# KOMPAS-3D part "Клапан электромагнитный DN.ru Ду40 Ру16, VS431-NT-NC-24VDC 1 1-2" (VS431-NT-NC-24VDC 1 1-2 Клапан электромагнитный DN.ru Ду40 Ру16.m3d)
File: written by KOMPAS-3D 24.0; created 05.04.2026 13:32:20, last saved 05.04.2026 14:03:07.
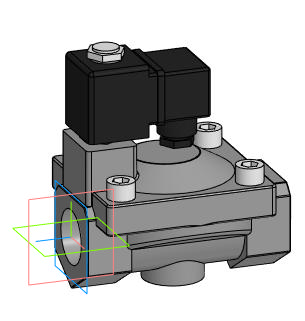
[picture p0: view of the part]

Document properties: Автор: artio; Полное имя файла: C:\Users\artio\OneDrive\Рабочий стол\Клапан электромагнитный DN.ru\VS431\VS431-NT-NC\VS431-NT-NC-24VDC\Ду40\VS431-NT-NC-24VDC 1 1-2 Клапан электромагнитный DN.ru Ду40 Ру16.m3d

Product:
- Body: Тело 1  | qty 1
    Масса: 3.859459
- Part/product: Клапан электромагнитный DN.ru Ду40 Ру16  | designation VS431-NT-NC-24VDC 1 1-2
    Масса: 2.285
    Раздел спецификации: Прочие изделия
    Примечание: D130-04751
    additional columns: ef56311e-7521-43dc-8291-0e6108b3d81d; artio; c; Шероховатость не задана; Да

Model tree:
1. Операция без истории:1

Expressions: VS431-NT-NC-24VDC 1 1-2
